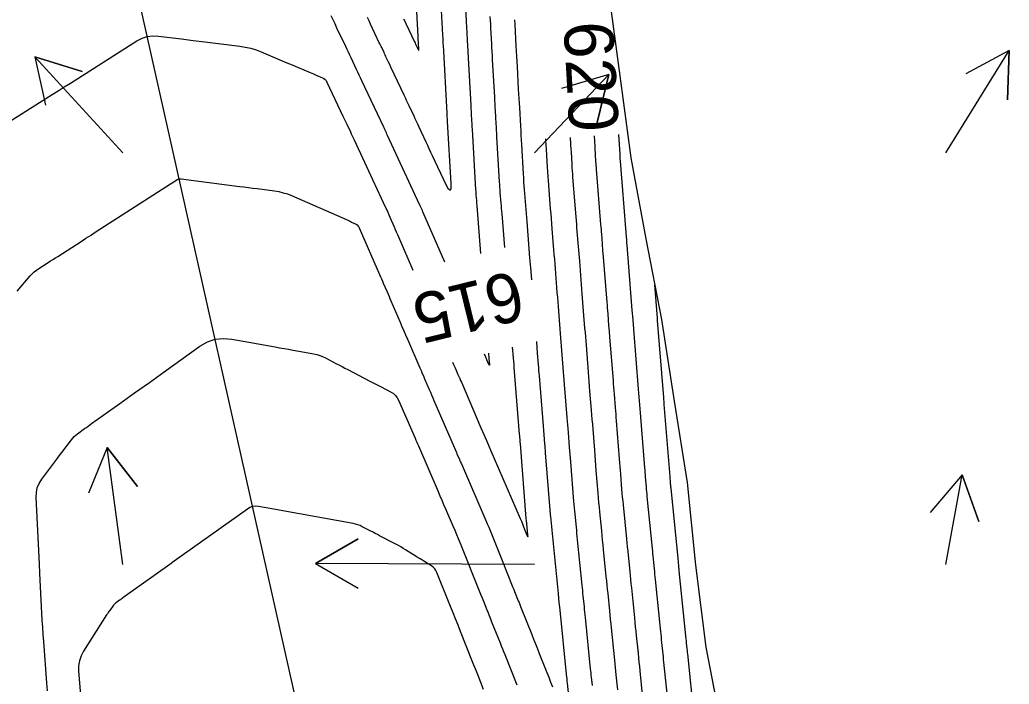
# Model space of a CAD drawing. Extents: x 954385 to 988206, y 1868364 to 1924553.
# Drawn here: x 958094.6 to 958214.8, y 1918454.4 to 1918535.1 of the extents above; entities that cross this region are included whole.
import ezdxf

# ---------------------------------------------------------------- set-up
doc = ezdxf.new("R2010")
doc.units = 0
for name, color, linetype in [('Default', 7, 'Continuous'), ('Ex_Contour Labels', 7, 'Continuous'), ('Ex_Major Contours', 7, 'Continuous'), ('Ex_Minor Contours', 7, 'Continuous'), ('Perimeter', 7, 'Continuous'), ('Slopes', 7, 'Continuous')]:
    doc.layers.add(name, color=color, linetype=linetype)

msp = doc.modelspace()

# ---------------------------------------------------------------- linework, layer by layer
at = {"layer": 'Default'}
msp.add_line((958200.6, 1918129.72), (957843.86, 1919719.4), dxfattribs=at)
at = {"layer": 'Ex_Major Contours'}
for points in [[(958148.53, 1918540.54), (958148.84, 1918534.99), (958148.86, 1918534.67), (958148.87, 1918534.34), (958148.89, 1918534.02), (958148.91, 1918533.7), (958148.98, 1918532.42), (958149, 1918532.1), (958149.02, 1918531.78), (958149.03, 1918531.45), (958149.05, 1918531.13), (958149.4, 1918524.71), (958149.41, 1918524.46), (958149.43, 1918524.22), (958149.44, 1918523.97), (958149.45, 1918523.73), (958149.51, 1918522.75), (958149.53, 1918522.51), (958149.54, 1918522.27), (958149.55, 1918522.02), (958149.57, 1918521.78), (958150, 1918514.42), (958150.01, 1918514.26), (958150.02, 1918514.1), (958150.03, 1918513.94), (958150.04, 1918513.78), (958150.09, 1918513.14), (958150.12, 1918512.82), (958150.14, 1918512.49), (958150.6, 1918506.7)], [(958146.24, 1918505.63), (958143.59, 1918511.75), (958143.52, 1918511.9), (958143.41, 1918512.16), (958143.38, 1918512.24), (958143.34, 1918512.32), (958143.27, 1918512.49), (958143.25, 1918512.54), (958143.23, 1918512.58), (958143.21, 1918512.62), (958143.19, 1918512.66), (958139.3, 1918521.01), (958139.22, 1918521.18), (958139.15, 1918521.35), (958138.99, 1918521.69), (958138.95, 1918521.77), (958138.91, 1918521.86), (958138.87, 1918521.94), (958138.83, 1918522.03), (958136.16, 1918527.68), (958136, 1918528.02), (958135.83, 1918528.37), (958135.67, 1918528.71), (958135.51, 1918529.06), (958134.86, 1918530.44), (958134.7, 1918530.78), (958134.53, 1918531.13), (958134.37, 1918531.47), (958134.21, 1918531.82), (958133.14, 1918534.08), (958132.91, 1918534.57), (958132.68, 1918535.07), (958132.44, 1918535.56)], [(958170.29, 1918453.08), (958169.99, 1918456), (958169.93, 1918456.53), (958169.88, 1918457.07), (958169.82, 1918457.6), (958169.77, 1918458.14), (958169.55, 1918460.29), (958169.5, 1918460.82), (958169.44, 1918461.36), (958169.39, 1918461.89), (958169.33, 1918462.43), (958168.96, 1918466.1), (958168.91, 1918466.59), (958168.86, 1918467.09), (958168.81, 1918467.58), (958168.76, 1918468.08), (958168.56, 1918470.06), (958168.51, 1918470.56), (958168.46, 1918471.05), (958168.41, 1918471.55), (958168.36, 1918472.05), (958167.95, 1918476.18), (958167.91, 1918476.65), (958167.86, 1918477.11), (958167.82, 1918477.58), (958167.78, 1918478.04), (958167.64, 1918479.9), (958167.6, 1918480.37), (958167.56, 1918480.83), (958167.52, 1918481.3), (958167.49, 1918481.76), (958167.12, 1918486.37), (958167.09, 1918486.77), (958167.06, 1918487.18), (958167.02, 1918487.59), (958166.99, 1918488), (958166.86, 1918489.63), (958166.83, 1918490.03), (958166.8, 1918490.44), (958166.76, 1918490.85), (958166.73, 1918491.25), (958166.31, 1918496.54), (958166.25, 1918497.25), (958166.2, 1918497.96), (958166.09, 1918499.38), (958166.06, 1918499.73), (958166.03, 1918500.09), (958166, 1918500.44), (958165.97, 1918500.8), (958165.5, 1918506.74), (958165.47, 1918507.03), (958165.45, 1918507.32), (958165.43, 1918507.61), (958165.41, 1918507.89), (958165.31, 1918509.05), (958165.29, 1918509.33), (958165.27, 1918509.62), (958165.25, 1918509.91), (958165.22, 1918510.2), (958164.69, 1918516.93), (958164.67, 1918517.16), (958164.65, 1918517.39), (958164.64, 1918517.61), (958164.62, 1918517.84), (958164.57, 1918518.76), (958164.56, 1918518.99), (958164.54, 1918519.21), (958164.53, 1918519.44), (958164.52, 1918519.67), (958164.44, 1918520.97)], [(958151.57, 1918494.58), (958151.62, 1918493.96), (958151.62, 1918493.89), (958151.68, 1918493.23), (958151.68, 1918493.15), (958151.67, 1918493.12), (958151.64, 1918493.14), (958151.61, 1918493.21), (958151.36, 1918493.78), (958151.22, 1918494.12), (958151.07, 1918494.46)]]:
    msp.add_lwpolyline(points, dxfattribs=at)
at = {"layer": 'Ex_Minor Contours'}
for points in [[(958145.53, 1918541.36), (958145.93, 1918534.02), (958145.94, 1918533.86), (958145.95, 1918533.69), (958145.96, 1918533.52), (958145.97, 1918533.35), (958146, 1918532.68), (958146.01, 1918532.51), (958146.02, 1918532.34), (958146.03, 1918532.17), (958146.04, 1918532.01), (958146.49, 1918523.73), (958146.49, 1918523.65), (958146.5, 1918523.56), (958146.5, 1918523.48), (958146.51, 1918523.39), (958146.53, 1918522.96), (958146.54, 1918522.79), (958146.55, 1918522.71), (958146.99, 1918515.18), (958146.98, 1918514.57), (958146.89, 1918514.34), (958146.69, 1918514.49), (958146.4, 1918515.03), (958144.75, 1918518.57), (958144.56, 1918518.98), (958144.36, 1918519.4), (958144.17, 1918519.82), (958143.97, 1918520.23), (958143.11, 1918522.1), (958142.96, 1918522.42), (958142.81, 1918522.73), (958142.66, 1918523.05), (958142.51, 1918523.37), (958141.91, 1918524.64), (958141.76, 1918524.96), (958141.61, 1918525.28), (958141.46, 1918525.6), (958141.31, 1918525.91), (958139.69, 1918529.34), (958139.56, 1918529.63), (958139.42, 1918529.92), (958139.14, 1918530.51), (958139.07, 1918530.65), (958139, 1918530.8), (958138.93, 1918530.95), (958138.87, 1918531.09), (958138.58, 1918531.7), (958138.51, 1918531.85), (958138.44, 1918532), (958138.37, 1918532.15), (958138.29, 1918532.3), (958137.24, 1918534.55), (958137.04, 1918534.96), (958136.85, 1918535.37)], [(958141.24, 1918535.21), (958141.38, 1918534.91), (958141.51, 1918534.62), (958142.55, 1918532.42), (958142.63, 1918532.27), (958142.7, 1918532.11), (958143, 1918531.48), (958143.05, 1918531.39), (958143.08, 1918531.36), (958143.1, 1918531.4), (958143.1, 1918531.51), (958143.03, 1918532.89), (958143.02, 1918533.06), (958142.52, 1918542.18)], [(958153.53, 1918507.42), (958153.2, 1918511.53), (958153.17, 1918511.85), (958153.15, 1918512.18), (958153.12, 1918512.5), (958153.1, 1918512.82), (958152.99, 1918514.11), (958152.97, 1918514.44), (958152.94, 1918514.76), (958152.92, 1918515.08), (958152.9, 1918515.41), (958152.59, 1918520.85), (958152.56, 1918521.25), (958152.54, 1918521.66), (958152.52, 1918522.06), (958152.49, 1918522.46), (958152.4, 1918524.07), (958152.38, 1918524.47), (958152.35, 1918524.88), (958152.33, 1918525.28), (958152.31, 1918525.68), (958152.06, 1918530.26), (958152.03, 1918530.73), (958152.01, 1918531.21), (958151.98, 1918531.68), (958151.96, 1918532.16), (958151.85, 1918534.05), (958151.83, 1918534.53), (958151.8, 1918535), (958151.78, 1918535.48)], [(958156.82, 1918503.5), (958156.74, 1918504.52), (958156.7, 1918504.94), (958156.67, 1918505.35), (958156.64, 1918505.76), (958156.6, 1918506.17), (958156.25, 1918510.57), (958156.22, 1918511.05), (958156.18, 1918511.54), (958156.14, 1918512.02), (958156.1, 1918512.51), (958155.95, 1918514.45), (958155.91, 1918514.93), (958155.87, 1918515.42), (958155.84, 1918515.9), (958155.81, 1918516.39), (958155.61, 1918519.92), (958155.57, 1918520.49), (958155.54, 1918521.05), (958155.51, 1918521.61), (958155.48, 1918522.17), (958155.35, 1918524.41), (958155.31, 1918524.97), (958155.28, 1918525.53), (958155.25, 1918526.09), (958155.22, 1918526.65), (958155.07, 1918529.39), (958155.04, 1918530.02), (958155, 1918530.64), (958154.97, 1918531.27), (958154.93, 1918531.9), (958154.79, 1918534.5), (958154.76, 1918535.08)], [(958092.48, 1918522.16), (958097.78, 1918525.51), (958098.53, 1918525.99), (958099.27, 1918526.46), (958100.02, 1918526.93), (958100.77, 1918527.4), (958108.84, 1918532.52), (958109.46, 1918532.84), (958110.09, 1918533.04), (958110.76, 1918533.13), (958111.45, 1918533.1), (958114.26, 1918532.75), (958115.67, 1918532.58), (958117.08, 1918532.41), (958121.34, 1918531.88), (958122.01, 1918531.77), (958122.67, 1918531.62), (958123.31, 1918531.43), (958123.94, 1918531.18), (958127.06, 1918529.86), (958127.7, 1918529.59), (958128.34, 1918529.32), (958129.91, 1918528.66), (958130.09, 1918528.58), (958130.28, 1918528.5), (958130.46, 1918528.42), (958130.64, 1918528.35), (958131.38, 1918528.03), (958131.55, 1918527.94), (958131.7, 1918527.83), (958131.82, 1918527.69), (958131.92, 1918527.52), (958133.87, 1918523.37), (958133.99, 1918523.13), (958134.1, 1918522.89), (958134.21, 1918522.66), (958134.33, 1918522.42), (958134.78, 1918521.46), (958134.89, 1918521.22), (958135, 1918520.98), (958135.11, 1918520.74), (958135.23, 1918520.5), (958136.49, 1918517.8), (958136.74, 1918517.27), (958136.98, 1918516.74), (958137.23, 1918516.21), (958137.48, 1918515.67), (958139.05, 1918512.29), (958139.19, 1918512), (958139.32, 1918511.7), (958139.46, 1918511.41), (958139.59, 1918511.11), (958140.1, 1918509.92), (958140.23, 1918509.62), (958140.36, 1918509.32), (958140.49, 1918509.02), (958140.62, 1918508.72), (958142.37, 1918504.68)], [(958161.49, 1918520.8), (958161.5, 1918520.6), (958161.52, 1918520.21), (958161.54, 1918519.83), (958161.56, 1918519.44), (958161.59, 1918519.05), (958161.68, 1918517.5), (958161.7, 1918517.12), (958161.73, 1918516.73), (958161.75, 1918516.34), (958161.78, 1918515.96), (958162.17, 1918511.16), (958162.2, 1918510.71), (958162.24, 1918510.26), (958162.27, 1918509.81), (958162.31, 1918509.36), (958162.45, 1918507.56), (958162.49, 1918507.11), (958162.52, 1918506.66), (958162.56, 1918506.21), (958162.6, 1918505.76), (958162.91, 1918501.78), (958162.96, 1918501.26), (958163, 1918500.74), (958163.04, 1918500.22), (958163.08, 1918499.7), (958163.24, 1918497.63), (958163.29, 1918497.11), (958163.33, 1918496.59), (958163.37, 1918496.07), (958163.41, 1918495.56), (958163.67, 1918492.29), (958163.72, 1918491.71), (958163.76, 1918491.13), (958163.81, 1918490.56), (958163.85, 1918489.98), (958164.04, 1918487.68), (958164.08, 1918487.1), (958164.13, 1918486.52), (958164.18, 1918485.95), (958164.22, 1918485.37), (958164.43, 1918482.8), (958164.47, 1918482.18), (958164.52, 1918481.56), (958164.57, 1918480.94), (958164.62, 1918480.32), (958164.84, 1918477.6), (958164.89, 1918477.03), (958164.94, 1918476.46), (958164.99, 1918475.88), (958165.05, 1918475.31), (958165.27, 1918473.02), (958165.33, 1918472.45), (958165.39, 1918471.88), (958165.45, 1918471.3), (958165.5, 1918470.73), (958165.83, 1918467.48), (958165.88, 1918466.95), (958165.93, 1918466.43), (958165.99, 1918465.91), (958166.04, 1918465.39), (958166.25, 1918463.3), (958166.3, 1918462.78), (958166.36, 1918462.25), (958166.41, 1918461.73), (958166.46, 1918461.21), (958166.86, 1918457.31), (958166.91, 1918456.86), (958166.95, 1918456.41), (958167, 1918455.96), (958167.04, 1918455.51), (958167.23, 1918453.7)], [(958173.42, 1918451.77), (958172.88, 1918457.04), (958172.84, 1918457.38), (958172.81, 1918457.72), (958172.77, 1918458.07), (958172.74, 1918458.41), (958172.6, 1918459.78), (958172.56, 1918460.12), (958172.53, 1918460.46), (958172.49, 1918460.8), (958172.46, 1918461.15), (958171.85, 1918467.12), (958171.82, 1918467.43), (958171.79, 1918467.74), (958171.76, 1918468.06), (958171.73, 1918468.37), (958171.6, 1918469.61), (958171.57, 1918469.92), (958171.54, 1918470.23), (958171.51, 1918470.54), (958171.48, 1918470.85), (958170.84, 1918477.19), (958170.82, 1918477.48), (958170.79, 1918477.77), (958170.76, 1918478.06), (958170.74, 1918478.35), (958170.65, 1918479.52), (958170.62, 1918479.81), (958170.6, 1918480.1), (958170.58, 1918480.39), (958170.55, 1918480.68), (958170.02, 1918487.36), (958169.98, 1918487.84), (958169.95, 1918488.31), (958169.87, 1918489.27), (958169.83, 1918489.75), (958169.79, 1918490.22), (958169.21, 1918497.52), (958169.17, 1918498.1), (958169.09, 1918499.05), (958169.06, 1918499.43), (958169.03, 1918499.82), (958168.4, 1918507.72), (958168.38, 1918507.97), (958168.36, 1918508.23), (958168.31, 1918508.86), (958168.29, 1918509.11), (958168.28, 1918509.23), (958167.59, 1918517.9), (958167.58, 1918517.97), (958167.58, 1918518.04), (958167.57, 1918518.11), (958167.57, 1918518.18), (958167.55, 1918518.53), (958167.54, 1918518.74), (958167.4, 1918521.13)], [(958164.18, 1918454.23), (958164.08, 1918455.24), (958164.05, 1918455.5), (958164.02, 1918455.75), (958164, 1918456.01), (958163.97, 1918456.26), (958163.34, 1918462.49), (958163.31, 1918462.82), (958163.27, 1918463.15), (958163.24, 1918463.48), (958163.21, 1918463.8), (958163.07, 1918465.12), (958163.04, 1918465.45), (958163.01, 1918465.77), (958162.97, 1918466.1), (958162.94, 1918466.43), (958162.39, 1918471.92), (958162.35, 1918472.31), (958162.31, 1918472.7), (958162.28, 1918473.09), (958162.24, 1918473.47), (958162.08, 1918475.02), (958162.04, 1918475.41), (958162.01, 1918475.8), (958161.97, 1918476.19), (958161.94, 1918476.57), (958161.56, 1918481.4), (958161.52, 1918481.85), (958161.49, 1918482.3), (958161.45, 1918482.74), (958161.42, 1918483.19), (958161.27, 1918484.97), (958161.24, 1918485.42), (958161.2, 1918485.87), (958161.17, 1918486.31), (958161.13, 1918486.76), (958160.81, 1918490.8), (958160.77, 1918491.31), (958160.73, 1918491.83), (958160.69, 1918492.34), (958160.65, 1918492.85), (958160.48, 1918494.91), (958160.44, 1918495.42), (958160.4, 1918495.94), (958160.36, 1918496.45), (958160.32, 1918496.96), (958160.06, 1918500.24), (958160.01, 1918500.82), (958159.97, 1918501.39), (958159.92, 1918501.97), (958159.87, 1918502.55), (958159.69, 1918504.85), (958159.64, 1918505.43), (958159.6, 1918506), (958159.55, 1918506.58), (958159.51, 1918507.16), (958159.31, 1918509.68), (958159.26, 1918510.29), (958159.21, 1918510.9), (958159.16, 1918511.51), (958159.11, 1918512.12), (958158.88, 1918514.98), (958158.84, 1918515.53), (958158.8, 1918516.07), (958158.77, 1918516.62), (958158.73, 1918517.16), (958158.6, 1918519.34), (958158.57, 1918519.89), (958158.54, 1918520.44), (958158.53, 1918520.64)], [(958094.28, 1918502.13), (958095.88, 1918503.98), (958096.11, 1918504.22), (958096.36, 1918504.46), (958096.63, 1918504.67), (958096.91, 1918504.86), (958098.06, 1918505.6), (958098.35, 1918505.79), (958098.64, 1918505.97), (958098.93, 1918506.16), (958099.22, 1918506.34), (958102.07, 1918508.17), (958102.64, 1918508.54), (958103.21, 1918508.9), (958103.78, 1918509.27), (958104.35, 1918509.64), (958112.91, 1918515.14), (958113.33, 1918515.41), (958113.75, 1918515.68), (958113.86, 1918515.73), (958113.97, 1918515.77), (958114.09, 1918515.78), (958114.21, 1918515.78), (958121.32, 1918514.85), (958121.85, 1918514.78), (958122.38, 1918514.71), (958122.91, 1918514.64), (958123.44, 1918514.57), (958125.57, 1918514.3), (958126.09, 1918514.21), (958126.61, 1918514.08), (958127.12, 1918513.93), (958127.61, 1918513.73), (958134.39, 1918510.78), (958134.53, 1918510.72), (958134.66, 1918510.65), (958134.8, 1918510.59), (958134.93, 1918510.52), (958135.47, 1918510.24), (958135.6, 1918510.16), (958135.7, 1918510.07), (958135.79, 1918509.95), (958135.86, 1918509.82), (958138.32, 1918504.14), (958138.44, 1918503.87), (958138.55, 1918503.61), (958138.67, 1918503.34), (958138.78, 1918503.08), (958139.24, 1918502.02), (958139.35, 1918501.75), (958139.47, 1918501.49), (958139.58, 1918501.22), (958139.7, 1918500.96), (958140.82, 1918498.36), (958141.04, 1918497.84), (958141.27, 1918497.32), (958141.49, 1918496.8), (958141.72, 1918496.28), (958143.22, 1918492.8), (958143.36, 1918492.47), (958143.51, 1918492.14), (958143.65, 1918491.82), (958143.79, 1918491.49), (958144.36, 1918490.17), (958144.5, 1918489.84), (958144.65, 1918489.51), (958144.79, 1918489.18), (958144.93, 1918488.85), (958147.66, 1918482.54), (958147.73, 1918482.37), (958148.04, 1918481.67), (958148.09, 1918481.53), (958148.15, 1918481.4), (958148.21, 1918481.27), (958148.26, 1918481.14), (958151.24, 1918474.26), (958151.41, 1918473.86), (958151.58, 1918473.46), (958151.75, 1918473.05), (958151.91, 1918472.65), (958152.56, 1918471.03), (958152.73, 1918470.62), (958152.89, 1918470.22), (958153.05, 1918469.81), (958153.21, 1918469.41), (958154.44, 1918466.35), (958154.53, 1918466.12), (958154.62, 1918465.89), (958154.72, 1918465.66), (958154.81, 1918465.43), (958155.18, 1918464.52), (958155.27, 1918464.29), (958155.36, 1918464.06), (958155.45, 1918463.83), (958155.54, 1918463.6), (958156.81, 1918460.42), (958157.04, 1918459.84), (958157.27, 1918459.27), (958157.5, 1918458.69), (958157.73, 1918458.11), (958158.65, 1918455.81), (958158.88, 1918455.23), (958159.11, 1918454.65), (958159.34, 1918454.07)], [(958176.55, 1918450.45), (958175.76, 1918458.09), (958175.75, 1918458.23), (958175.73, 1918458.38), (958175.72, 1918458.53), (958175.7, 1918458.68), (958175.63, 1918459.42), (958175.6, 1918459.71), (958175.58, 1918459.86), (958174.74, 1918468.15), (958174.73, 1918468.28), (958174.71, 1918468.4), (958174.7, 1918468.53), (958174.69, 1918468.65), (958174.63, 1918469.28), (958174.6, 1918469.54), (958174.59, 1918469.66), (958173.74, 1918478.19), (958173.72, 1918478.31), (958173.71, 1918478.43), (958173.7, 1918478.54), (958173.69, 1918478.66), (958173.66, 1918479.13), (958173.64, 1918479.37), (958173.62, 1918479.6), (958172.92, 1918488.35), (958172.9, 1918488.63), (958172.87, 1918489.05), (958172.86, 1918489.19), (958172.11, 1918498.54), (958172.09, 1918498.83), (958171.77, 1918502.87)], [(958097.97, 1918453.56), (958097.89, 1918454.56), (958097.51, 1918459.57), (958097.45, 1918460.43), (958097.39, 1918461.3), (958097.34, 1918462.16), (958097.29, 1918463.03), (958097.06, 1918467.82), (958097, 1918469.02), (958096.6, 1918477.06), (958096.62, 1918477.67), (958096.74, 1918478.24), (958096.96, 1918478.78), (958097.29, 1918479.3), (958099.11, 1918481.72), (958099.32, 1918482), (958099.53, 1918482.28), (958099.74, 1918482.55), (958099.95, 1918482.83), (958100.88, 1918484.08), (958101.05, 1918484.28), (958101.23, 1918484.47), (958101.42, 1918484.64), (958101.63, 1918484.8), (958102.49, 1918485.42), (958102.7, 1918485.57), (958102.91, 1918485.72), (958103.13, 1918485.88), (958103.34, 1918486.03), (958106.76, 1918488.47), (958107.2, 1918488.79), (958107.65, 1918489.11), (958108.1, 1918489.44), (958108.55, 1918489.76), (958110.35, 1918491.04), (958110.8, 1918491.36), (958111.25, 1918491.68), (958111.69, 1918492), (958112.14, 1918492.32), (958116.5, 1918495.43), (958117.4, 1918495.96), (958118.34, 1918496.27), (958119.33, 1918496.39), (958120.37, 1918496.3), (958125.64, 1918495.35), (958126.18, 1918495.25), (958126.73, 1918495.15), (958127.27, 1918495.06), (958127.81, 1918494.96), (958130.32, 1918494.51), (958130.69, 1918494.42), (958131.05, 1918494.32), (958131.4, 1918494.18), (958131.75, 1918494.02), (958133.1, 1918493.31), (958133.44, 1918493.13), (958133.78, 1918492.96), (958134.12, 1918492.78), (958134.46, 1918492.6), (958137.16, 1918491.2), (958137.8, 1918490.86), (958138.44, 1918490.53), (958139.72, 1918489.87), (958140.01, 1918489.68), (958140.27, 1918489.45), (958140.48, 1918489.18), (958140.64, 1918488.87), (958142.63, 1918484.26), (958142.73, 1918484.03), (958142.84, 1918483.79), (958142.94, 1918483.56), (958143.04, 1918483.33), (958145.43, 1918477.78), (958145.66, 1918477.26), (958145.88, 1918476.74), (958146.11, 1918476.22), (958146.33, 1918475.7), (958147.23, 1918473.62), (958147.46, 1918473.1), (958147.68, 1918472.58), (958147.89, 1918472.06), (958148.1, 1918471.53), (958150.6, 1918465.32), (958150.77, 1918464.89), (958150.94, 1918464.46), (958151.36, 1918463.42), (958151.41, 1918463.3), (958151.46, 1918463.18), (958151.5, 1918463.06), (958151.55, 1918462.94), (958151.79, 1918462.34), (958151.94, 1918461.97), (958152.96, 1918459.4), (958153.11, 1918459.04), (958153.25, 1918458.69), (958153.39, 1918458.34), (958153.53, 1918457.98), (958155, 1918454.3)], [(958161.67, 1918449.48), (958161.16, 1918454.52), (958161.13, 1918454.75), (958161.11, 1918454.98), (958161.1, 1918455.1), (958161.09, 1918455.21), (958160.22, 1918463.78), (958160.19, 1918464.04), (958160.16, 1918464.31), (958160.11, 1918464.85), (958160.09, 1918464.98), (958160.08, 1918465.12), (958160.07, 1918465.25), (958160.05, 1918465.39), (958159.28, 1918473.11), (958159.24, 1918473.52), (958159.2, 1918473.93), (958159.12, 1918474.74), (958159.1, 1918474.94), (958159.08, 1918475.14), (958159.06, 1918475.34), (958159.04, 1918475.55), (958158.49, 1918482.48), (958158.47, 1918482.75), (958158.45, 1918483.03), (958158.43, 1918483.3), (958158.4, 1918483.57), (958158.32, 1918484.66), (958158.27, 1918485.21), (958158.23, 1918485.76), (958157.75, 1918491.83), (958157.72, 1918492.17), (958157.69, 1918492.52), (958157.67, 1918492.86), (958157.64, 1918493.21), (958157.53, 1918494.59), (958157.47, 1918495.28), (958157.42, 1918495.97), (958157.41, 1918496.02)], [(958147.2, 1918493.51), (958147.32, 1918493.22), (958147.5, 1918492.82), (958147.67, 1918492.41), (958147.76, 1918492.21), (958147.85, 1918492.01), (958148.06, 1918491.52), (958148.16, 1918491.29), (958148.26, 1918491.05), (958150.64, 1918485.54), (958151.05, 1918484.61), (958151.45, 1918483.68), (958151.85, 1918482.74), (958152.26, 1918481.81), (958155.42, 1918474.5), (958155.45, 1918474.42), (958155.49, 1918474.34), (958155.52, 1918474.25), (958155.55, 1918474.17), (958155.72, 1918473.75), (958155.82, 1918473.5), (958156.23, 1918472.48), (958156.3, 1918472.34), (958156.34, 1918472.29), (958156.36, 1918472.35), (958156.35, 1918472.51), (958156.17, 1918474.32), (958156.15, 1918474.45), (958156.15, 1918474.47), (958156.15, 1918474.48), (958156.15, 1918474.5), (958156.15, 1918474.52), (958155.43, 1918483.56), (958155.41, 1918483.76), (958155.39, 1918483.96), (958155.35, 1918484.55), (958155.33, 1918484.75), (958154.69, 1918492.86), (958154.66, 1918493.21), (958154.63, 1918493.56), (958154.56, 1918494.45), (958154.52, 1918494.97), (958154.49, 1918495.3)], [(958150.97, 1918453.74), (958150.3, 1918455.43), (958150.13, 1918455.85), (958149.96, 1918456.27), (958149.79, 1918456.7), (958149.62, 1918457.12), (958148.16, 1918460.8), (958147.86, 1918461.55), (958147.55, 1918462.31), (958147.25, 1918463.06), (958146.95, 1918463.81), (958145.28, 1918467.96), (958145.17, 1918468.2), (958145.02, 1918468.41), (958144.84, 1918468.6), (958144.62, 1918468.75), (958143.7, 1918469.33), (958143.47, 1918469.47), (958143.24, 1918469.61), (958143.01, 1918469.75), (958142.78, 1918469.9), (958141.49, 1918470.7), (958141.2, 1918470.88), (958140.91, 1918471.05), (958140.61, 1918471.22), (958140.3, 1918471.38), (958138.32, 1918472.41), (958138.06, 1918472.55), (958137.79, 1918472.69), (958137.53, 1918472.83), (958137.27, 1918472.96), (958136.22, 1918473.51), (958135.95, 1918473.64), (958135.67, 1918473.74), (958135.39, 1918473.83), (958135.11, 1918473.89), (958126.57, 1918475.43), (958125.46, 1918475.63), (958123.61, 1918475.96), (958123.25, 1918476), (958122.9, 1918475.95), (958122.57, 1918475.84), (958122.26, 1918475.66), (958113.36, 1918469.31), (958112.82, 1918468.92), (958112.27, 1918468.53), (958111.73, 1918468.14), (958111.18, 1918467.75), (958107.13, 1918464.86), (958107.03, 1918464.79), (958106.93, 1918464.72), (958106.83, 1918464.65), (958106.74, 1918464.58), (958106.35, 1918464.3), (958106.25, 1918464.23), (958106.17, 1918464.15), (958106.09, 1918464.07), (958106.01, 1918463.98), (958105.54, 1918463.35), (958105.44, 1918463.22), (958105.34, 1918463.08), (958105.25, 1918462.94), (958105.16, 1918462.8), (958102.35, 1918458.39), (958102.05, 1918457.83), (958101.85, 1918457.24), (958101.75, 1918456.63), (958101.75, 1918455.99), (958102.01, 1918452.58)]]:
    msp.add_lwpolyline(points, dxfattribs=at)
at = {"layer": 'Perimeter'}
msp.add_lwpolyline([(958166.17, 1918538.23), (958167.51, 1918528.28), (958168.87, 1918518.33), (958170.66, 1918508.49), (958172.59, 1918498.67), (958174.13, 1918488.77), (958175.69, 1918478.87), (958176.71, 1918468.85), (958177.97, 1918458.88), (958179.86, 1918449.06), (958179.87, 1918447.9), (958182.32, 1918439.36), (958183.91, 1918429.47), (958185.71, 1918419.63), (958187.13, 1918409.7), (958188.43, 1918399.74), (958190.03, 1918389.85), (958192.01, 1918380.04), (958194.13, 1918370.27), (958196.15, 1918360.48), (958197.73, 1918350.58), (958199.86, 1918340.81)], dxfattribs=at)
at = {"layer": 'Slopes'}
for points in [[(958107.13, 1918518.93), (958096.45, 1918530.59), (958102.17, 1918528.78), (958096.45, 1918530.59), (958097.75, 1918524.73)], [(958207.13, 1918518.93), (958214.83, 1918531.36), (958214.64, 1918525.36), (958214.83, 1918531.36), (958209.54, 1918528.52)], [(958157.13, 1918518.93), (958166.17, 1918528.45), (958164.77, 1918522.61), (958166.17, 1918528.45), (958160.42, 1918526.74)], [(958107.13, 1918468.93), (958105.24, 1918483.14), (958108.9, 1918478.39), (958105.24, 1918483.14), (958102.95, 1918477.59)], [(958207.13, 1918468.93), (958209.11, 1918479.8), (958211.13, 1918474.15), (958209.11, 1918479.8), (958205.23, 1918475.22)], [(958157.13, 1918468.93), (958130.52, 1918469.06), (958135.74, 1918472.04), (958130.52, 1918469.06), (958135.71, 1918466.04)]]:
    msp.add_lwpolyline(points, dxfattribs=at)

# ---------------------------------------------------------------- texts
at = {"layer": 'Ex_Contour Labels'}
for s, rotation, p in [('620', 273.2068, (958160.67, 1918534.71)), ('615', 193.7765, (958154.94, 1918504.68))]:
    msp.add_text(s, height=6, rotation=rotation, dxfattribs=at).set_placement(p)

doc.saveas('drawing.dxf')
